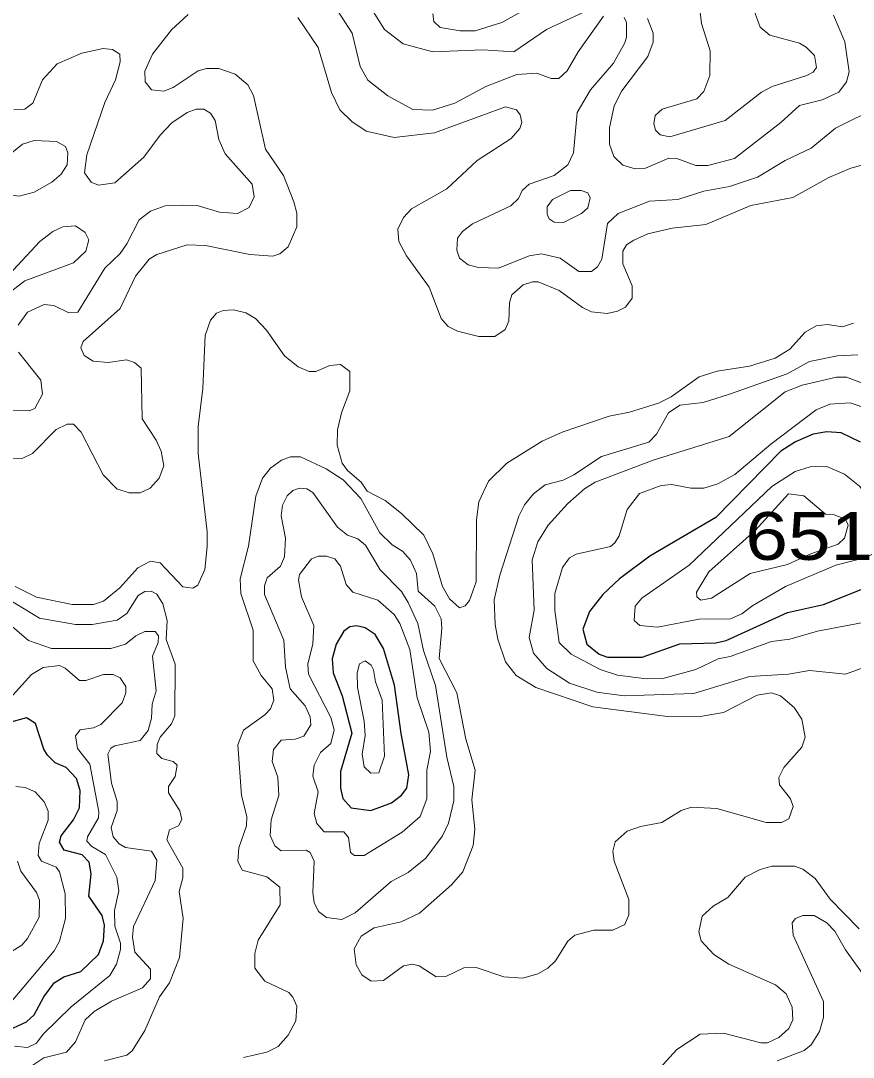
# Model space of a CAD drawing. Extents: x 577 to 602.9, y 7483.8 to 7511.6.
# Drawn here: x 587.677 to 589.071, y 7490.626 to 7492.363 of the extents above; entities that cross this region are included whole.
import ezdxf
from ezdxf.enums import TextEntityAlignment as Align

# ---------------------------------------------------------------- set-up
doc = ezdxf.new("R2010")
doc.units = 0
doc.header["$LTSCALE"] = 0.032
doc.layers.add('1', color=7, linetype='Continuous', lineweight=25)
doc.layers.add('2', color=7, linetype='Continuous', lineweight=13)
doc.layers.add('61', color=7, linetype='Continuous')

msp = doc.modelspace()

# ---------------------------------------------------------------- linework, layer by layer
at = {"layer": '1'}
for points in [[(589.0838, 7491.6568), (589.0511, 7491.6727), (589.0273, 7491.6743), (589.0042, 7491.6703), (588.9748, 7491.6576), (588.9502, 7491.6417), (588.8412, 7491.5304), (588.7307, 7491.4659), (588.6798, 7491.4278), (588.652, 7491.4015), (588.6297, 7491.3729), (588.6186, 7491.3435), (588.6249, 7491.318), (588.6456, 7491.3013), (588.6599, 7491.2966), (588.718, 7491.2966), (588.7808, 7491.3188), (588.8412, 7491.3204), (588.8587, 7491.3244), (588.9613, 7491.3713), (589.0217, 7491.3848), (589.0933, 7491.4135)], [(587.6572, 7490.6716), (587.6866, 7490.6851), (587.6993, 7490.697), (587.7153, 7490.7272), (587.7327, 7490.7503), (587.7487, 7490.7606), (587.7773, 7490.7694), (587.8067, 7490.798), (587.8154, 7490.8211), (587.817, 7490.8473), (587.8131, 7490.8632), (587.7908, 7490.8958), (587.7948, 7490.9332), (587.7916, 7490.9531), (587.7797, 7490.965), (587.7494, 7490.9729), (587.7415, 7490.9865), (587.7447, 7490.9968), (587.7653, 7491.0238), (587.7749, 7491.0437), (587.7765, 7491.0731), (587.7701, 7491.093), (587.7526, 7491.1113), (587.7343, 7491.1192), (587.7216, 7491.132), (587.7153, 7491.1423), (587.7017, 7491.1852), (587.6866, 7491.1948), (587.658, 7491.1868)]]:
    msp.add_lwpolyline(points, dxfattribs=at)
msp.add_lwpolyline([(588.3138, 7491.1687), (588.3029, 7491.2497), (588.2846, 7491.3109), (588.2703, 7491.3347), (588.2536, 7491.3459), (588.2393, 7491.3491), (588.2281, 7491.3475), (588.2178, 7491.3403), (588.2051, 7491.318), (588.1987, 7491.2934), (588.2003, 7491.2703), (588.2154, 7491.2314), (588.2313, 7491.1693), (588.2122, 7491.1049), (588.2122, 7491.0771), (588.2162, 7491.0596), (588.2305, 7491.0437), (588.2631, 7491.0397), (588.2981, 7491.0525), (588.3148, 7491.0652), (588.3236, 7491.0771), (588.3267, 7491.0994)], close=True, dxfattribs=at)
at = {"layer": '2'}
for points in [[(588.5693, 7492.409), (588.4826, 7492.3605), (588.4381, 7492.3462), (588.4126, 7492.3462), (588.3792, 7492.3518), (588.3689, 7492.3621), (588.3673, 7492.3748)], [(588.9017, 7492.3907), (588.9152, 7492.3526), (588.9319, 7492.339), (588.9812, 7492.3255), (588.9923, 7492.3192), (589.0066, 7492.3049), (589.0098, 7492.285), (589.0042, 7492.277), (588.9939, 7492.2715), (588.9358, 7492.2532), (588.9176, 7492.2436), (588.8571, 7492.1959), (588.7641, 7492.1689), (588.7482, 7492.1721), (588.7402, 7492.18), (588.7371, 7492.1904), (588.7394, 7492.2047), (588.7514, 7492.215), (588.8094, 7492.2325), (588.8213, 7492.2444), (588.8309, 7492.2715), (588.8317, 7492.3128), (588.8174, 7492.3589), (588.8118, 7492.4066)], [(588.2011, 7492.3899), (588.2321, 7492.3422), (588.2456, 7492.2866), (588.2584, 7492.2635), (588.2918, 7492.2373), (588.3335, 7492.2144), (588.3663, 7492.2132), (588.4039, 7492.2253), (588.4556, 7492.2532), (588.508, 7492.273), (588.5414, 7492.2754), (588.5653, 7492.2667), (588.578, 7492.2667), (588.5923, 7492.2794), (588.6106, 7492.3112), (588.6528, 7492.3709)], [(588.6464, 7492.3899), (588.5573, 7492.3486), (588.5025, 7492.3112), (588.4508, 7492.3144), (588.3673, 7492.3112), (588.3172, 7492.3247), (588.2862, 7492.3486), (588.2671, 7492.3788)], [(587.6548, 7491.6282), (587.6803, 7491.6298), (587.6962, 7491.6377), (587.7359, 7491.6783), (587.7542, 7491.687), (587.7653, 7491.687), (587.7781, 7491.6735), (587.8146, 7491.6019), (587.8377, 7491.5789), (587.8584, 7491.5717), (587.8767, 7491.5717), (587.8934, 7491.5797), (587.9085, 7491.5964), (587.9164, 7491.617), (587.9117, 7491.6417), (587.9037, 7491.66), (587.8799, 7491.6958), (587.8783, 7491.7808), (587.8671, 7491.7904), (587.8536, 7491.7951), (587.8234, 7491.7904), (587.798, 7491.7928), (587.7828, 7491.8023), (587.7773, 7491.815), (587.7813, 7491.8254), (587.8433, 7491.881), (587.8687, 7491.9351), (587.8918, 7491.9637), (587.9045, 7491.9717), (587.9554, 7491.9876), (587.9864, 7491.9868), (588.0604, 7491.9717), (588.0993, 7491.9685), (588.1105, 7491.9725), (588.1248, 7491.9844), (588.1391, 7492.0178), (588.1391, 7492.0409), (588.1343, 7492.0599), (588.1168, 7492.1037), (588.0866, 7492.1482), (588.0667, 7492.2381), (588.0572, 7492.2556), (588.0357, 7492.2738), (588.0087, 7492.2834), (587.988, 7492.2834), (587.9737, 7492.2794), (587.9323, 7492.2516), (587.9164, 7492.2452), (587.8958, 7492.2476), (587.8854, 7492.2611), (587.8846, 7492.2786), (587.8973, 7492.3072), (587.9292, 7492.3478), (587.957, 7492.374)], [(588.6329, 7491.8755), (588.6178, 7491.8826), (588.5788, 7491.9112), (588.5438, 7491.9256), (588.5343, 7491.9256), (588.5184, 7491.9208), (588.4993, 7491.9041), (588.4953, 7491.8906), (588.4945, 7491.8596), (588.4882, 7491.846), (588.4707, 7491.8341), (588.4444, 7491.8341), (588.4086, 7491.8429), (588.3927, 7491.8508), (588.3808, 7491.8643), (588.3609, 7491.9168), (588.3228, 7491.9693), (588.31, 7491.9931), (588.3085, 7492.0138), (588.318, 7492.0337), (588.3315, 7492.048), (588.3904, 7492.0814), (588.4412, 7492.1291), (588.4985, 7492.1657), (588.5128, 7492.1824), (588.516, 7492.1927), (588.5136, 7492.2055), (588.5072, 7492.2142), (588.489, 7492.219), (588.3697, 7492.1752), (588.3021, 7492.1673), (588.2552, 7492.1784), (588.2313, 7492.1943), (588.2114, 7492.2142), (588.1971, 7492.2428), (588.1749, 7492.3184), (588.1407, 7492.3685)], [(588.6878, 7492.3685), (588.6917, 7492.3605), (588.6917, 7492.3359), (588.6885, 7492.3263), (588.6695, 7492.2921), (588.6313, 7492.2476), (588.609, 7492.2094), (588.6027, 7492.1418), (588.5931, 7492.122), (588.5701, 7492.1037), (588.5287, 7492.0894), (588.5168, 7492.079), (588.5104, 7492.0655), (588.4977, 7492.0528), (588.4333, 7492.0226), (588.4166, 7492.0098), (588.4086, 7491.9987), (588.4071, 7491.9788), (588.4118, 7491.9653), (588.4261, 7491.9542), (588.4436, 7491.9494), (588.477, 7491.9486), (588.5287, 7491.9693), (588.5494, 7491.9725), (588.5804, 7491.9653), (588.6114, 7491.9431), (588.6329, 7491.9431), (588.6432, 7491.951), (588.6504, 7491.9637), (588.6599, 7492.0234), (588.6774, 7492.0401), (588.7299, 7492.0607), (588.7776, 7492.0639), (588.8213, 7492.0774), (588.8643, 7492.0854), (588.9112, 7492.1013), (588.9573, 7492.1291), (589.0011, 7492.1498), (589.0416, 7492.1832), (589.1148, 7492.2198)], [(589.0384, 7492.3724), (589.0575, 7492.3279), (589.0647, 7492.2778), (589.0599, 7492.2611), (589.0472, 7492.2436), (589.0193, 7492.2309), (588.9812, 7492.2214), (588.9502, 7492.1927), (588.8722, 7492.1323), (588.8277, 7492.1204), (588.8078, 7492.1204), (588.776, 7492.1323), (588.7625, 7492.1331), (588.7235, 7492.1164), (588.706, 7492.1148), (588.6854, 7492.1212), (588.6703, 7492.1355), (588.6631, 7492.1562), (588.6631, 7492.184), (588.6711, 7492.2206), (588.6838, 7492.246), (588.7275, 7492.3033), (588.7363, 7492.3271), (588.7363, 7492.3422), (588.7267, 7492.3669)], [(588.019, 7492.1403), (588.0087, 7492.1641), (588.0023, 7492.1959), (587.9944, 7492.2086), (587.9832, 7492.215), (587.9705, 7492.215), (587.9554, 7492.2094), (587.93, 7492.1919), (587.9101, 7492.1713), (587.883, 7492.1347), (587.8345, 7492.0917), (587.8067, 7492.0878), (587.7948, 7492.0925), (587.7836, 7492.1084), (587.7876, 7492.1387), (587.8178, 7492.2261), (587.8353, 7492.2643), (587.8433, 7492.2945), (587.8425, 7492.3072), (587.8306, 7492.3152), (587.8146, 7492.3168), (587.7789, 7492.3088), (587.7375, 7492.2913), (587.7129, 7492.2643), (587.697, 7492.2253), (587.6834, 7492.215), (587.6652, 7492.2142)], [(587.6723, 7491.8532), (587.6882, 7491.8747), (587.716, 7491.8874), (587.732, 7491.8858), (587.7574, 7491.8739), (587.7725, 7491.8747), (587.8178, 7491.9486), (587.8433, 7491.9733), (587.8544, 7491.9892), (587.8751, 7492.0297), (587.8942, 7492.044), (587.9188, 7492.0528), (587.9482, 7492.0544), (587.9721, 7492.0536), (588.0095, 7492.0424), (588.0397, 7492.0401), (588.0596, 7492.0504), (588.0675, 7492.0679), (588.0643, 7492.0894), (588.019, 7492.1403)], [(589.106, 7492.1267), (589.0671, 7492.1164), (589.0305, 7492.1005), (588.97, 7492.0671), (588.9001, 7492.0536), (588.8245, 7492.0218), (588.7681, 7492.0154), (588.7275, 7492.0059), (588.7037, 7491.9955), (588.6917, 7491.9876), (588.6854, 7491.9772), (588.6854, 7491.9558), (588.7013, 7491.9192), (588.7013, 7491.8985), (588.6901, 7491.8834), (588.6766, 7491.8763), (588.6591, 7491.8723), (588.6329, 7491.8755)], [(587.6341, 7491.9136), (587.7089, 7491.9931), (587.7304, 7492.0098), (587.7471, 7492.0178), (587.7685, 7492.0194), (587.7844, 7492.0083), (587.7908, 7491.9963), (587.786, 7491.9772), (587.7653, 7491.9574), (587.6834, 7491.9271), (587.6477, 7491.9001)], [(589.0718, 7491.8564), (589.0535, 7491.85), (589.0281, 7491.854), (589.009, 7491.8516), (588.9907, 7491.8413), (588.9653, 7491.8126), (588.9406, 7491.7975), (588.8977, 7491.784), (588.8436, 7491.7761), (588.8134, 7491.7665), (588.7665, 7491.7331), (588.745, 7491.722), (588.6965, 7491.7069), (588.6623, 7491.7005), (588.5836, 7491.6735), (588.5502, 7491.6584), (588.4913, 7491.6218), (588.4603, 7491.5916), (588.4444, 7491.5566), (588.4405, 7491.5264), (588.4397, 7491.423), (588.4285, 7491.3912), (588.4214, 7491.3825), (588.4118, 7491.3793), (588.3951, 7491.3944), (588.3832, 7491.4151), (588.3673, 7491.4699), (588.3522, 7491.5009), (588.3148, 7491.5375), (588.287, 7491.559), (588.2568, 7491.5749), (588.2472, 7491.59), (588.2242, 7491.6091), (588.2154, 7491.6218), (588.2067, 7491.652), (588.2075, 7491.6775), (588.2138, 7491.7061), (588.2281, 7491.7427), (588.2281, 7491.7753), (588.2122, 7491.7872), (588.1947, 7491.7856), (588.1709, 7491.7753), (588.1598, 7491.7753), (588.1415, 7491.7832), (588.1184, 7491.8015), (588.0882, 7491.8444), (588.0699, 7491.8643), (588.054, 7491.8739), (588.0333, 7491.8786), (588.0158, 7491.8778), (588.0047, 7491.8731), (587.9944, 7491.8611), (587.9856, 7491.8357), (587.9816, 7491.7466), (587.9737, 7491.683), (587.9737, 7491.6377), (587.9888, 7491.5065), (587.9888, 7491.4818), (587.9852, 7491.4434), (587.9733, 7491.4171), (587.9649, 7491.4119), (587.9482, 7491.4143), (587.9101, 7491.4548), (587.8942, 7491.4572), (587.8727, 7491.4461), (587.8425, 7491.4127), (587.8154, 7491.3904), (587.7987, 7491.3848), (587.763, 7491.3848), (587.7033, 7491.3968), (587.6675, 7491.4151)], [(587.6333, 7491.7117), (587.6906, 7491.7093), (587.7001, 7491.7132), (587.7129, 7491.7371), (587.7105, 7491.761), (587.6731, 7491.8079)], [(589.079, 7491.8031), (589.0448, 7491.8015), (588.9979, 7491.792), (588.9605, 7491.7713), (588.8643, 7491.7371), (588.8198, 7491.7236), (588.7808, 7491.7188), (588.7617, 7491.7061), (588.7418, 7491.6703), (588.7291, 7491.6568)], [(588.6416, 7491.2377), (588.5963, 7491.2528), (588.5581, 7491.2775), (588.5359, 7491.3029), (588.5287, 7491.3292), (588.5367, 7491.3753), (588.5335, 7491.4596), (588.543, 7491.4898), (588.5605, 7491.5176), (588.5931, 7491.5542), (588.621, 7491.5789), (588.6392, 7491.59), (588.7363, 7491.6266), (588.8635, 7491.6663), (588.9573, 7491.7411), (588.9859, 7491.7522), (589.0432, 7491.7657), (589.0599, 7491.7657), (589.1935, 7491.7156)], [(589.0973, 7491.7124), (589.0663, 7491.7228), (589.0321, 7491.7204), (589.009, 7491.7109), (588.9335, 7491.6536), (588.873, 7491.6027), (588.8444, 7491.5868), (588.8213, 7491.5797), (588.7991, 7491.5797), (588.7673, 7491.586), (588.7498, 7491.5844), (588.7132, 7491.5709), (588.6925, 7491.5439), (588.679, 7491.5001), (588.6718, 7491.4882), (588.6647, 7491.4818), (588.6074, 7491.4691), (588.5963, 7491.4628), (588.5844, 7491.4469), (588.5717, 7491.4031), (588.5717, 7491.3745), (588.5788, 7491.3212), (588.5987, 7491.3013), (588.6472, 7491.2759), (588.6766, 7491.2664), (588.7251, 7491.26), (588.7522, 7491.2608), (588.8078, 7491.2759), (588.8452, 7491.2934), (588.8651, 7491.2974), (588.9343, 7491.3228), (588.9653, 7491.3268), (589.0114, 7491.3403), (589.0997, 7491.357)], [(588.7291, 7491.6568), (588.6496, 7491.6329), (588.6035, 7491.6019), (588.5852, 7491.5932), (588.555, 7491.5852), (588.5359, 7491.5701), (588.5208, 7491.5518), (588.5112, 7491.5327), (588.4794, 7491.4341), (588.4699, 7491.3928), (588.4715, 7491.3514), (588.4762, 7491.3268), (588.489, 7491.2886), (588.5065, 7491.2656), (588.5399, 7491.2457), (588.6353, 7491.2131), (588.7601, 7491.1972), (588.8118, 7491.1964), (588.8539, 7491.2035), (588.9104, 7491.233), (588.9343, 7491.2369), (588.9494, 7491.2314), (588.9724, 7491.2123), (588.9851, 7491.1924), (588.9907, 7491.1622), (588.9851, 7491.1455), (588.9549, 7491.1113), (588.947, 7491.0946), (588.9478, 7491.0827), (588.9661, 7491.0588), (588.9708, 7491.0461), (588.9637, 7491.0254), (588.951, 7491.0191), (588.9255, 7491.0191), (588.8428, 7491.0429), (588.8007, 7491.0453), (588.7832, 7491.0397), (588.7506, 7491.0191), (588.7148, 7491.0127), (588.6925, 7491.0047), (588.6726, 7490.9872), (588.6687, 7490.9713), (588.6711, 7490.9546), (588.6957, 7490.8902), (588.6957, 7490.8648), (588.6885, 7490.8481), (588.6687, 7490.8386), (588.6369, 7490.8386), (588.6051, 7490.8306), (588.5931, 7490.8203), (588.5725, 7490.7877), (588.5597, 7490.7749), (588.543, 7490.7654), (588.5176, 7490.7582), (588.4858, 7490.7606), (588.4397, 7490.7765), (588.419, 7490.7757), (588.3888, 7490.7614), (588.3729, 7490.7606), (588.3442, 7490.7789), (588.3331, 7490.7821), (588.318, 7490.7789), (588.2846, 7490.7543), (588.2639, 7490.7535), (588.248, 7490.7638), (588.2385, 7490.7805), (588.2353, 7490.8075), (588.2472, 7490.829), (588.2687, 7490.8425), (588.314, 7490.8529), (588.345, 7490.8672), (588.3983, 7490.9149), (588.4174, 7490.9364), (588.4349, 7490.9809), (588.4373, 7491.0079), (588.4325, 7491.0572), (588.4381, 7491.1073), (588.4222, 7491.159), (588.4071, 7491.2369), (588.3776, 7491.2942), (588.3824, 7491.3451), (588.3808, 7491.361), (588.3705, 7491.3817), (588.3426, 7491.4071), (588.3395, 7491.4365), (588.3299, 7491.4588), (588.3164, 7491.4739), (588.2989, 7491.485), (588.2782, 7491.5049), (588.2464, 7491.5622), (588.217, 7491.594), (588.1884, 7491.6123), (588.1454, 7491.6321), (588.1287, 7491.6321), (588.1136, 7491.6266), (588.0953, 7491.6131), (588.0818, 7491.5964), (588.0707, 7491.5661), (588.058, 7491.4826), (588.0445, 7491.4278), (588.0453, 7491.4031)], [(587.9045, 7491.4023), (587.895, 7491.4071), (587.8846, 7491.4063), (587.8735, 7491.3999), (587.8544, 7491.3697), (587.8385, 7491.3586), (587.7964, 7491.3514), (587.7685, 7491.3514), (587.7081, 7491.3618), (587.6437, 7491.4007)], [(587.817, 7490.6199), (587.8544, 7490.6294), (587.8632, 7490.6366), (587.8846, 7490.6708), (587.9093, 7490.7272), (587.926, 7490.7503), (587.9427, 7490.7932), (587.949, 7490.8584), (587.9419, 7490.9038), (587.9482, 7490.9268), (587.9482, 7490.9427), (587.9212, 7490.9904), (587.926, 7491.0071), (587.9411, 7491.0135), (587.9466, 7491.0246), (587.9435, 7491.0389), (587.9244, 7491.0692), (587.9244, 7491.0795), (587.9355, 7491.0962), (587.9387, 7491.1153), (587.9323, 7491.1216), (587.9133, 7491.1264), (587.9045, 7491.1352), (587.9053, 7491.1503), (587.9101, 7491.1622), (587.9292, 7491.1845), (587.9347, 7491.198), (587.9355, 7491.2846), (587.9204, 7491.326), (587.922, 7491.3578), (587.9148, 7491.3856), (587.9045, 7491.4023)], [(588.0453, 7491.4031), (588.0659, 7491.3419), (588.0659, 7491.2902), (588.0794, 7491.2656), (588.0977, 7491.2433), (588.1009, 7491.2242), (588.0953, 7491.2099), (588.0858, 7491.1996), (588.05, 7491.1741), (588.0405, 7491.1495), (588.0468, 7491.0644), (588.0556, 7491.0294), (588.0548, 7491.0135), (588.0421, 7490.9769), (588.0405, 7490.9546), (588.0476, 7490.9395), (588.089, 7490.9284), (588.1105, 7490.9109), (588.1113, 7490.8815), (588.0747, 7490.8219), (588.0691, 7490.7996), (588.0691, 7490.7749), (588.0858, 7490.7535), (588.1256, 7490.7344), (588.1327, 7490.7264), (588.1391, 7490.7113), (588.1375, 7490.6867), (588.1248, 7490.6628), (588.1081, 7490.6437), (588.089, 7490.6342), (588.05, 7490.6254)], [(587.6389, 7491.3673), (587.6898, 7491.3244), (587.728, 7491.3109), (587.8274, 7491.3109), (587.852, 7491.318), (587.8695, 7491.3324), (587.8846, 7491.3395), (587.9021, 7491.3395), (587.9077, 7491.3324), (587.9069, 7491.3212), (587.8973, 7491.2982), (587.9037, 7491.2401), (587.8966, 7491.2178), (587.8958, 7491.194), (587.8902, 7491.1733), (587.8767, 7491.1566), (587.8345, 7491.1479), (587.8274, 7491.1439), (587.8226, 7491.1336), (587.829, 7491.0851), (587.8385, 7491.0548), (587.8385, 7491.0397), (587.8282, 7491.0111), (587.8313, 7490.9952), (587.8417, 7490.9833), (587.852, 7490.9777), (587.8958, 7490.9713), (587.9045, 7490.9562), (587.9021, 7490.922), (587.8655, 7490.8449), (587.864, 7490.8274), (587.8679, 7490.802), (587.8942, 7490.7733)], [(589.1092, 7491.2862), (589.0583, 7491.2679), (588.9979, 7491.2743), (588.9629, 7491.2679), (588.8977, 7491.264), (588.8046, 7491.2353), (588.6878, 7491.2314), (588.6416, 7491.2377)], [(587.7884, 7490.9952), (587.8067, 7491.027), (587.8075, 7491.0373), (587.7924, 7491.1169), (587.7717, 7491.1431), (587.7685, 7491.1646), (587.7765, 7491.1749), (587.7987, 7491.1781), (587.8107, 7491.1837), (587.8465, 7491.2202), (587.8528, 7491.2369), (587.8528, 7491.2473), (587.8433, 7491.2616), (587.8313, 7491.2672), (587.8154, 7491.2672), (587.786, 7491.2576), (587.7749, 7491.2576), (587.751, 7491.2783), (587.7415, 7491.2823), (587.7145, 7491.2791), (587.6946, 7491.2672), (587.6636, 7491.233)], [(587.6683, 7491.0795), (587.6842, 7491.0779), (587.7009, 7491.0707), (587.716, 7491.054), (587.7224, 7491.0381), (587.7224, 7491.023), (587.7073, 7490.9841), (587.7057, 7490.9642), (587.7113, 7490.9546), (587.7359, 7490.9443), (587.7415, 7490.9364), (587.751, 7490.8998), (587.7518, 7490.8584), (587.7415, 7490.8203), (587.7327, 7490.8044), (587.6548, 7490.7121)], [(587.666, 7490.6445), (587.6882, 7490.6421), (587.7033, 7490.6493), (587.7145, 7490.6644), (587.7614, 7490.7105), (587.8258, 7490.763), (587.8369, 7490.7821), (587.8441, 7490.8067), (587.8441, 7490.8171), (587.8345, 7490.8457), (587.8337, 7490.8719), (587.8409, 7490.9046), (587.8377, 7490.9276), (587.8186, 7490.9658), (587.7956, 7490.9793), (587.7876, 7490.988), (587.7884, 7490.9952)], [(587.6715, 7490.9546), (587.6771, 7490.9379), (587.7033, 7490.9022), (587.7081, 7490.8894), (587.7073, 7490.8608), (587.6882, 7490.825), (587.6787, 7490.8139), (587.6596, 7490.802)], [(588.7466, 7490.6072), (588.776, 7490.639), (588.815, 7490.6644), (588.8539, 7490.666), (588.9168, 7490.6501), (588.9279, 7490.6501), (588.947, 7490.6588), (588.9637, 7490.6739), (588.97, 7490.6883), (588.9692, 7490.7097), (588.9589, 7490.732), (588.9414, 7490.7471), (588.8627, 7490.7821), (588.838, 7490.798), (588.8166, 7490.8211), (588.8126, 7490.8362), (588.8182, 7490.8624), (588.8365, 7490.8791), (588.8611, 7490.8934), (588.8905, 7490.9276), (588.9152, 7490.9403), (588.9351, 7490.9459), (588.9732, 7490.9459), (588.9867, 7490.9411), (589.0074, 7490.9252), (589.0329, 7490.891), (589.0814, 7490.8409)], [(589.0965, 7490.7527), (589.0583, 7490.8059), (589.0408, 7490.837), (589.0273, 7490.8513), (589.0058, 7490.8632), (588.9867, 7490.8632), (588.9748, 7490.8584), (588.9692, 7490.8513), (588.9708, 7490.8306), (589.0217, 7490.7193), (589.0217, 7490.6922), (589.0146, 7490.6692), (589.0011, 7490.6469), (588.9891, 7490.6374), (588.9438, 7490.6199)], [(587.8942, 7490.7733), (587.8942, 7490.7574), (587.8806, 7490.7423), (587.829, 7490.7201), (587.7995, 7490.7026), (587.7844, 7490.6883), (587.7685, 7490.6517), (587.7534, 7490.6342), (587.7153, 7490.6246), (587.697, 7490.6127), (587.6882, 7490.5936), (587.6938, 7490.5682), (587.6914, 7490.5531), (587.6691, 7490.5213)]]:
    msp.add_lwpolyline(points, dxfattribs=at)
for points in [[(587.6739, 7492.0695), (587.6993, 7492.0758), (587.7288, 7492.0925), (587.7447, 7492.1061), (587.7542, 7492.122), (587.7558, 7492.1418), (587.7518, 7492.1522), (587.7367, 7492.1609), (587.6993, 7492.1625), (587.6795, 7492.1562), (587.662, 7492.1418), (587.6461, 7492.1196), (587.6413, 7492.0989), (587.6437, 7492.0846), (587.662, 7492.0711)], [(588.5589, 7492.0393), (588.5621, 7492.0313), (588.5701, 7492.0257), (588.586, 7492.025), (588.6162, 7492.0401), (588.6265, 7492.0496), (588.6305, 7492.0663), (588.6265, 7492.075), (588.6154, 7492.079), (588.5979, 7492.079), (588.5677, 7492.0639), (588.5589, 7492.0512)], [(588.974, 7491.6075), (588.9351, 7491.5828), (588.7967, 7491.4508), (588.7172, 7491.3952), (588.706, 7491.3817), (588.7045, 7491.3578), (588.714, 7491.3498), (588.7434, 7491.3467), (588.8134, 7491.3602), (588.8659, 7491.361), (588.885, 7491.3689), (588.9032, 7491.3832), (588.9581, 7491.4151), (589.0424, 7491.4508), (589.0901, 7491.4628), (589.1148, 7491.4739), (589.1394, 7491.4985), (589.1426, 7491.516), (589.1315, 7491.5319), (589.1012, 7491.5574), (589.0818, 7491.583), (589.0566, 7491.6031), (589.0273, 7491.6162), (588.9992, 7491.6153)], [(588.151, 7491.1638), (588.1367, 7491.159), (588.1128, 7491.1574), (588.1001, 7491.1415), (588.0977, 7491.1216), (588.1073, 7491.0954), (588.1089, 7491.0644), (588.0961, 7491.0238), (588.0946, 7490.9976), (588.1025, 7490.9801), (588.1128, 7490.9721), (588.155, 7490.9729), (588.1613, 7490.969), (588.1685, 7490.9546), (588.1661, 7490.9022), (588.1685, 7490.8855), (588.1757, 7490.8704), (588.1892, 7490.86), (588.2146, 7490.8568), (588.2369, 7490.868), (588.2973, 7490.9205), (588.3259, 7490.9356), (588.3554, 7490.9594), (588.3832, 7490.9968), (588.3935, 7491.0183), (588.4023, 7491.0556), (588.4023, 7491.0795), (588.3904, 7491.1288), (588.3713, 7491.2489), (588.3514, 7491.3077), (588.3419, 7491.353), (588.3259, 7491.388), (588.3148, 7491.4063), (588.279, 7491.4429), (588.2544, 7491.4842), (588.2417, 7491.4946), (588.2242, 7491.5009), (588.2075, 7491.5145), (588.1661, 7491.5725), (588.1558, 7491.5789), (588.1439, 7491.5797), (588.1327, 7491.5757), (588.1232, 7491.5669), (588.1152, 7491.551), (588.1128, 7491.5335), (588.12, 7491.4962), (588.1184, 7491.4644), (588.112, 7491.4492), (588.0898, 7491.4294), (588.085, 7491.4158), (588.085, 7491.4015), (588.1176, 7491.3252), (588.12, 7491.2799), (588.1279, 7491.2433), (588.1534, 7491.2147), (588.1613, 7491.1964), (588.1629, 7491.1829)], [(589.0392, 7491.5351), (589.0583, 7491.528), (589.0631, 7491.5176), (589.0567, 7491.4962), (589.0464, 7491.4858), (589.0003, 7491.4699), (588.9613, 7491.4516), (588.8985, 7491.4365), (588.8341, 7491.3952), (588.8158, 7491.392), (588.8094, 7491.3976), (588.8086, 7491.4055), (588.8293, 7491.4397), (588.9072, 7491.5089), (588.9629, 7491.5701), (588.9885, 7491.5667), (589.0249, 7491.5359)], [(588.1685, 7491.1153), (588.1661, 7491.097), (588.1749, 7491.0707), (588.1685, 7491.0342), (588.1725, 7491.0175), (588.1852, 7491.0039), (588.2178, 7491.0039), (588.2258, 7490.9944), (588.2289, 7490.969), (588.2361, 7490.9642), (588.252, 7490.9642), (588.3156, 7491.0032), (588.3458, 7491.0294), (588.357, 7491.0588), (588.357, 7491.1073), (588.3633, 7491.1383), (588.3601, 7491.1709), (588.3411, 7491.2282), (588.3283, 7491.3093), (588.3116, 7491.353), (588.3021, 7491.3681), (588.2751, 7491.392), (588.2329, 7491.4055), (588.2218, 7491.4182), (588.2122, 7491.4492), (588.2027, 7491.4612), (588.1892, 7491.4659), (588.1757, 7491.4659), (588.1637, 7491.4612), (588.1439, 7491.4349), (588.1423, 7491.4254), (588.147, 7491.3976), (588.1677, 7491.3498), (588.1661, 7491.3188), (588.1574, 7491.2846), (588.159, 7491.2679), (588.1963, 7491.1956), (588.2019, 7491.1749), (588.1963, 7491.1519), (588.1788, 7491.1367)], [(588.252, 7491.1892), (588.2536, 7491.1654), (588.2488, 7491.1336), (588.252, 7491.1129), (588.2631, 7491.1018), (588.2766, 7491.1025), (588.2862, 7491.1304), (588.2822, 7491.2242), (588.2711, 7491.2552), (588.2679, 7491.2751), (588.2639, 7491.2831), (588.2536, 7491.2902), (588.244, 7491.2854), (588.2401, 7491.2703), (588.2409, 7491.2457)]]:
    msp.add_lwpolyline(points, close=True, dxfattribs=at)

# ---------------------------------------------------------------- texts
at = {"layer": '61', "width": 1.2}
msp.add_text('651', height=0.08, dxfattribs=at).set_placement((588.9977, 7491.4596), align=Align.CENTER)

doc.saveas('drawing.dxf')
